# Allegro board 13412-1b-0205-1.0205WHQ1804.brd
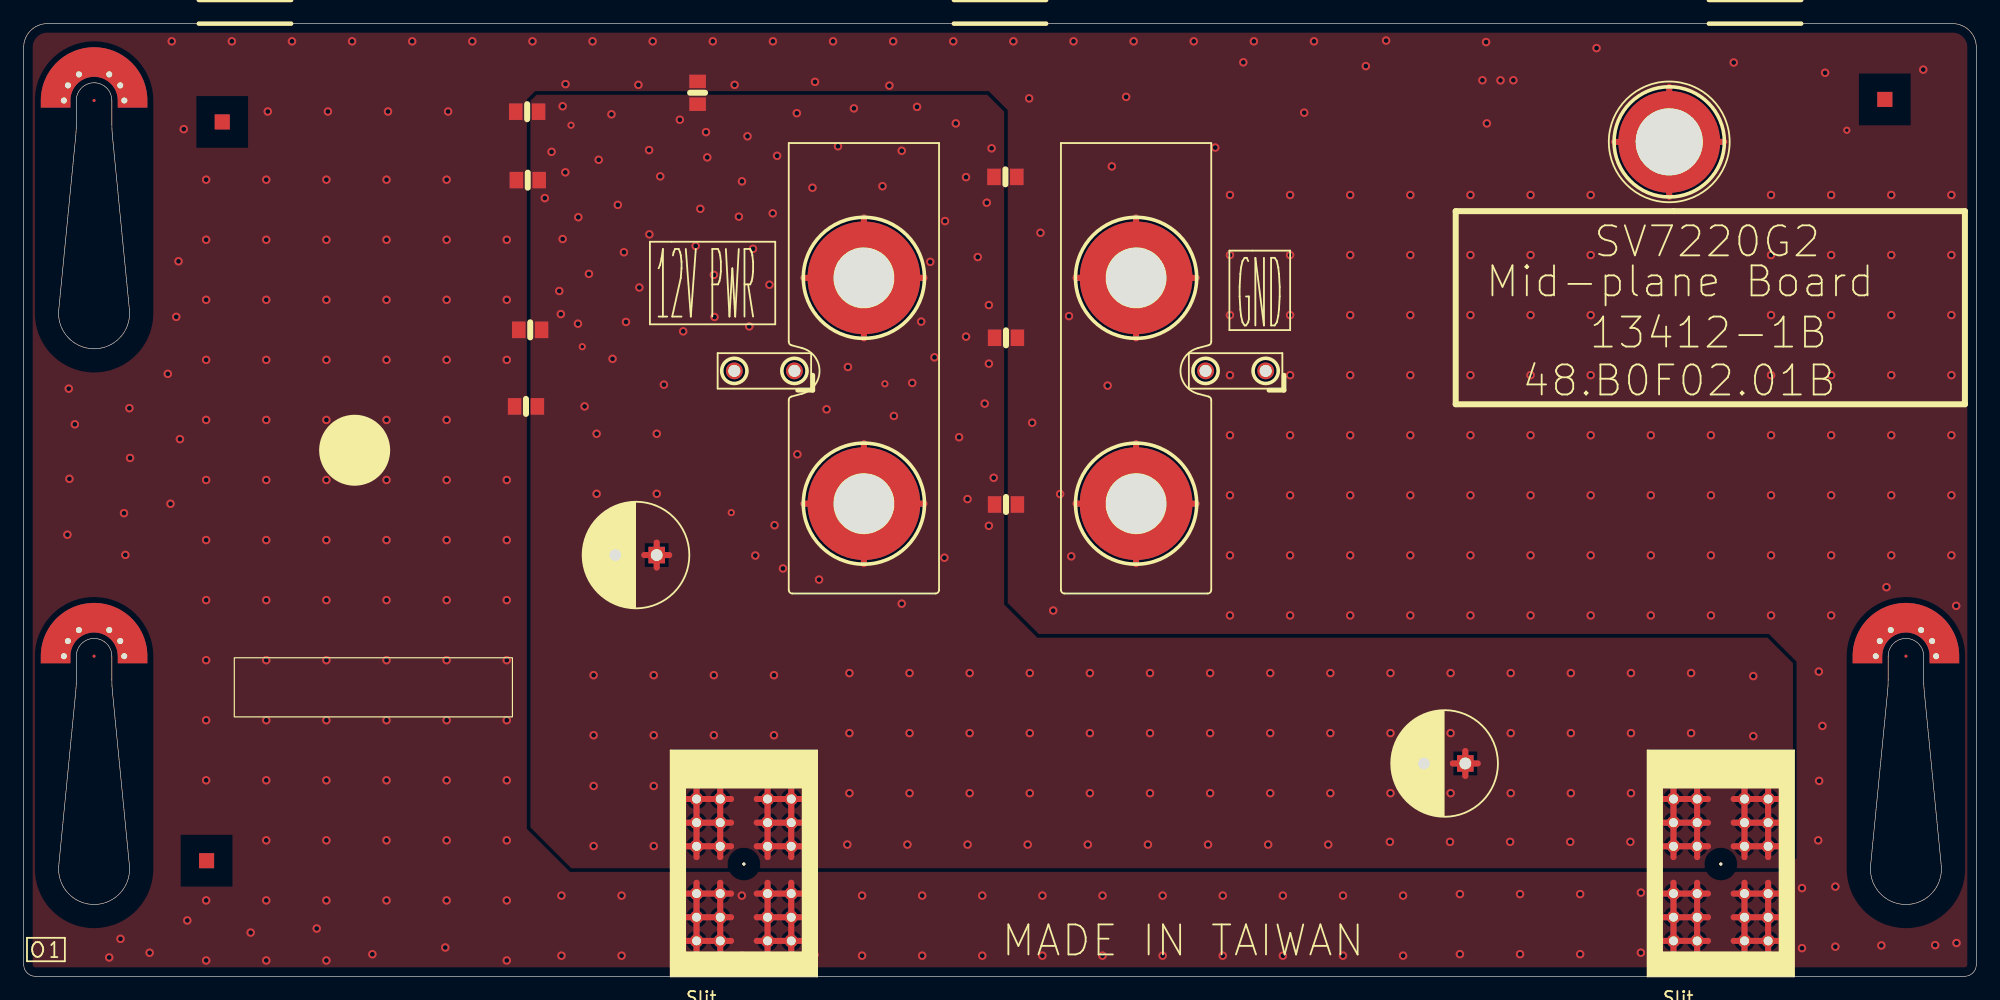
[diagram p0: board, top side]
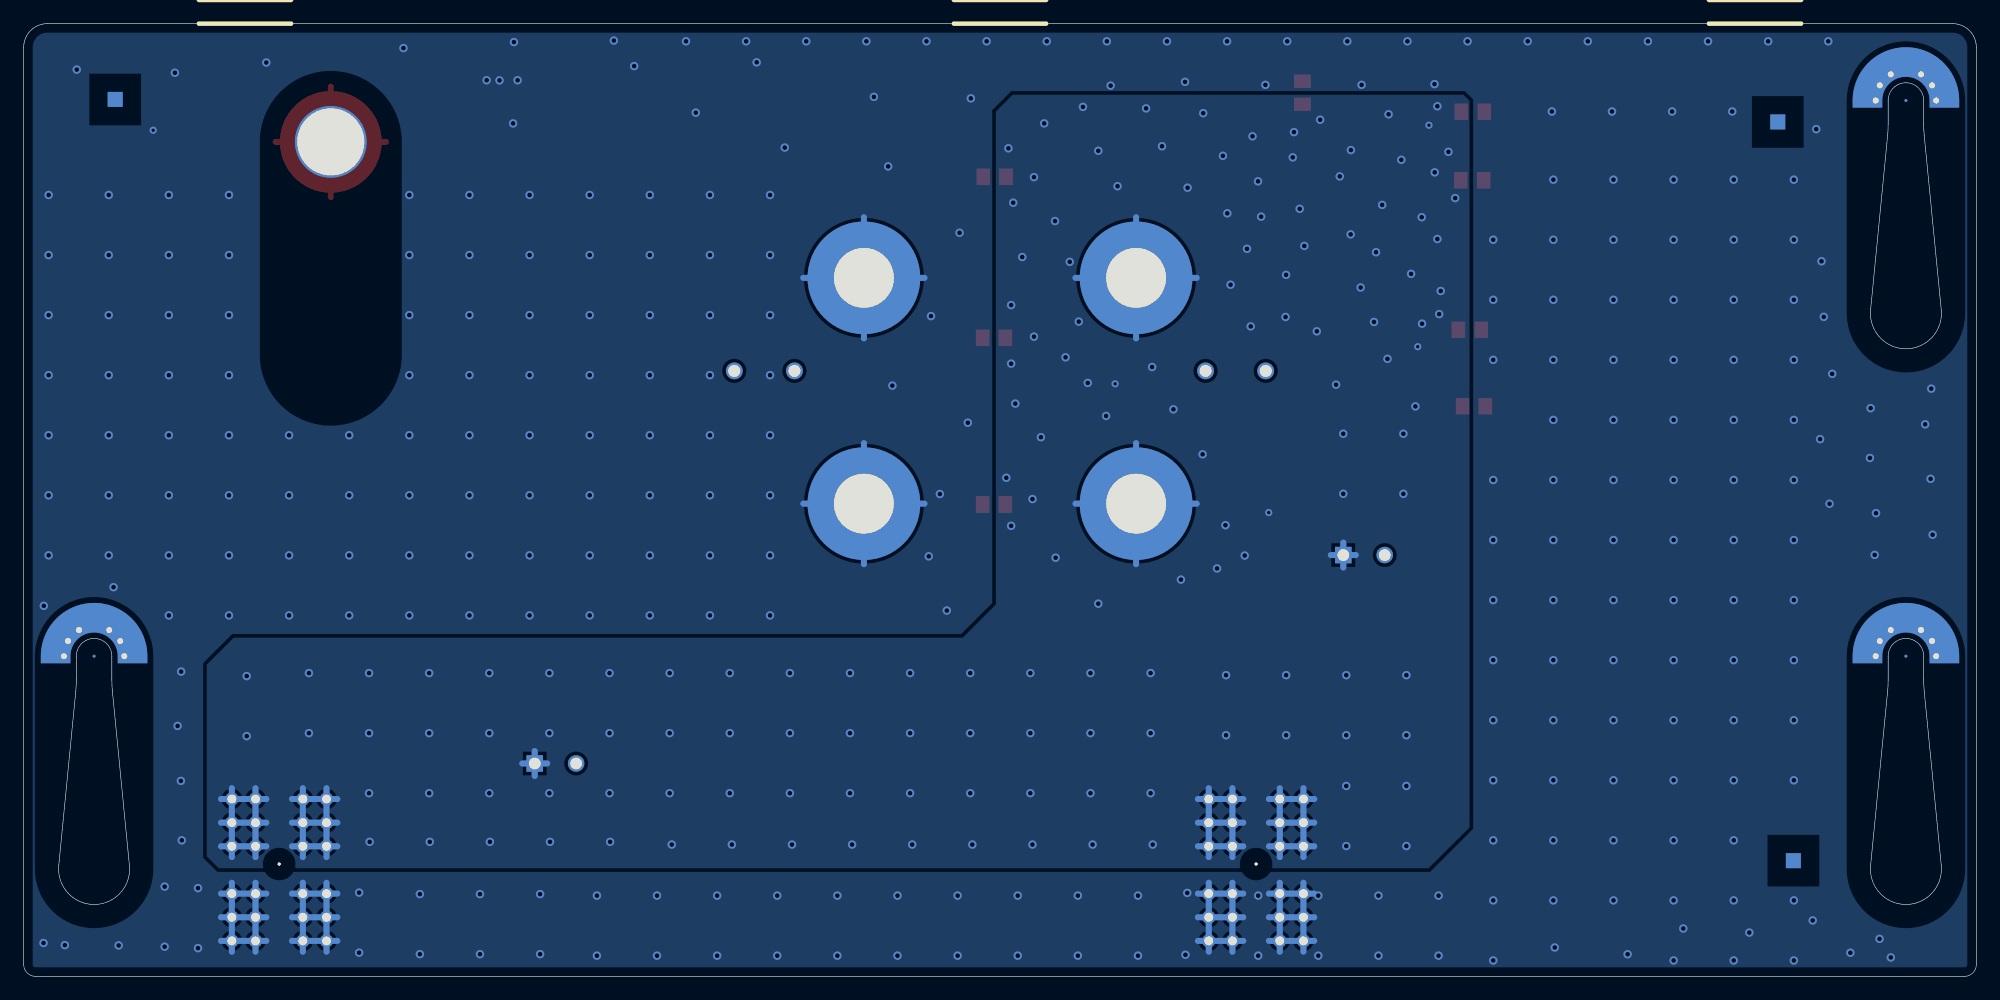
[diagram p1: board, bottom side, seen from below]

Outline 165 x 80.58 mm; copper layers: TOP, L2GND, L3GND, BOTTOM. Coordinates in mm from the lower left corner of the outline.
Outline path: 0,78.58 0,1 arc(0.29,0.29) 1,0 164,0 arc(164.71,0.29) 165,1 165,78.58 arc(164.41,79.99) 163,80.58 2,80.58 arc(0.59,79.99) 0,78.58 ; 2.96,56.37 4.4,71.11 arc(4.44,71.59) 4.45,72.08 4.45,74.08 arc(5.95,75.58) 7.45,74.08 7.45,72.08 arc(7.46,71.59) 7.5,71.11 8.94,56.37 arc(5.95,53.08) 2.96,56.37 ; 2.96,9.37 4.4,24.11 arc(4.44,24.59) 4.45,25.08 4.45,27.08 arc(5.95,28.58) 7.45,27.08 7.45,25.08 arc(7.46,24.59) 7.5,24.11 8.94,9.37 arc(5.95,6.08) 2.96,9.37 ; 156.06,9.37 157.5,24.11 arc(157.54,24.59) 157.55,25.08 157.55,27.08 arc(159.05,28.58) 160.55,27.08 160.55,25.08 arc(160.56,24.59) 160.6,24.11 162.04,9.37 arc(159.05,6.08) 156.06,9.37

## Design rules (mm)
constraint set DEFAULT: min track width 0.127
nets with their own width: min track width 0.508; nets GND

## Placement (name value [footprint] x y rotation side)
BH1  STF375R199H50-GP  [STF375R199H50]  71 59.08 0 top
BH2  STF375R199H50-GP  [STF375R199H50]  71 39.98 0 top
BH3  STF375R199H50-GP  [STF375R199H50]  94 59.08 0 top
BH4  STF375R199H50-GP  [STF375R199H50]  94 39.98 0 top
C1  SC10U25V5KX-GP  [C805H56]  42.55 73.13 270 top
C2  SC10U25V5KX-GP  [C805H56]  83.01 39.91 90 top
C3  SC1U25V5KX-1GP  [C805H58]  82.96 67.62 90 top
C4  SC1U25V5KX-1GP  [C805H58]  83.01 54.01 90 top
C5  SC1U25V5KX-1GP  [C805H58]  42.45 48.21 270 top
C6  SC1U25V5KX-1GP  [C805H58]  42.8 54.68 270 top
C7  SC1U25V5KX-1GP  [C805H58]  56.95 74.73 180 top
C8  SC1U25V5KX-1GP  [C805H58]  42.6 67.34 270 top
CN1  FCI-CONN24-6R-1-GP  [PREFIT-24P-119293H418]  60.86 9.5 0 top
CN2  FCI-CONN24-6R-1-GP  [PREFIT-24P-119293H418]  143.41 9.5 0 top
CN3  AMP-CON2-13-GP  [G800U305032D1EU]  62.59 51.21 180 top
CN4  AMP-CON2-13-GP  [G800U305032D1EU]  102.41 51.21 180 top
H1  GEN276R237X886-6-F-A-S-GP  [GEN276R237X886-6-F-A-S]  5.95 27.08 0 top
H2  STFT339B239R223H453-GP  [STFT339B239R223H453]  139.05 70.58 0 top
H3  GEN276R237X886-6-F-A-S-GP  [GEN276R237X886-6-F-A-S]  159.05 27.08 0 top
H4  GEN276R237X886-6-F-A-S-GP  [GEN276R237X886-6-F-A-S]  5.95 74.08 0 top
NOREF  -  []  1.88 167.43 0 top
NOREF#2  -  []  0 0 0 top
NOREF#3  -  []  0 -1.72 0 top
NOREF#4  -  [unnamed#2]  15.46 9.78 0 top
NOREF#5  -  []  0 -1.72 0 top
NOREF#6  -  [unnamed#2]  16.78 72.27 0 top
NOREF#7  -  []  1.88 2.27 0 top
NOREF#8  -  []  20.14 42.09 0 top
NOREF#9  -  []  0 -1.72 0 top
NOREF#10  -  []  0 -1.72 0 top
NOREF#11  -  []  0 -1.72 0 top
NOREF#12  -  []  0 0 0 top
NOREF#13  -  []  -7 146.48 0 top
NOREF#14  -  [unnamed#2]  157.27 74.17 0 top
NOREF#15  -  []  1.88 84.85 0 top
NOREF#16  -  [unnamed#2]  157.27 74.17 180 bottom
NOREF#17  -  [unnamed#2]  15.46 9.78 180 bottom
NOREF#18  -  [unnamed#2]  16.78 72.27 180 bottom
TC1  E270U16VM-9-GP  [ECAP-138D8H355]  120.07 18.01 90 top
TC2  E270U16VM-9-GP  [ECAP-138D8H355]  51.74 35.63 90 top

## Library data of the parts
BH1-BH4 = STF375R199H50: tolerance: 34.64W05.001
C1 C2 = C805H56: tolerance: 78.10622.51L
C3-C8 = C805H58: tolerance: 78.10522.21L
CN1 CN2 = PREFIT-24P-119293H418: tolerance: 20.82091.024
CN3 CN4 = G800U305032D1EU: tolerance: 25.60037.081
H1 H3 H4 = GEN276R237X886-6-F-A-S: tolerance: ZZ.SCREW.B11
H2 = STFT339B239R223H453: tolerance: ZZ.SCREW.601
TC1 TC2 = ECAP-138D8H355: tolerance: 09.2271D.25L

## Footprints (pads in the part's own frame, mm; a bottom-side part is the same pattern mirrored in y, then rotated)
C805H56
  rect 1.397x1.143 smd: 1(0,0.965) 2(0,-0.965)
C805H58
  rect 1.397x1.143 smd: 1(0,0.965) 2(0,-0.965)
ECAP-138D8H355
  rect 1.397x1.397 hole 0.991: 1(0,-1.75)
  round 1.397 hole 0.991: 2(0,1.75)
G800U305032D1EU
  round 1.422 hole 1.016: 1(-2.54,0) 2(2.54,0)
GEN276R237X886-6-F-A-S
  round 0.254 hole 0.025 unplated: (0,0)
  round 0.864 hole 0.508: 1(2.55,0) 2(2.21,1.28) 3(1.28,2.21) 4(-1.28,2.21) 5(-2.21,1.28) 6(-2.55,0)
PREFIT-24P-119293H418
  round 0.254 hole 2.134 unplated: (0,0)
  round 1.118 hole 0.75: P1_1(-4,1.5) P1_2(-4,3.5) P1_3(-4,5.5) P1_4(-2,1.5) P1_5(-2,3.5) P1_6(-2,5.5) P2_1(4,1.5) P2_2(4,3.5) P2_3(4,5.5) P2_4(2,1.5) P2_5(2,3.5) P2_6(2,5.5) P3_1(4,-6.5) P3_2(4,-4.5) P3_3(4,-2.5) P3_4(2,-6.5) P3_5(2,-4.5) P3_6(2,-2.5) P4_1(-4,-6.5) P4_2(-4,-4.5) P4_3(-4,-2.5) P4_4(-2,-6.5) P4_5(-2,-4.5) P4_6(-2,-2.5)
STF375R199H50
  round 9.525 hole 5.055: 1(0,0)
STFT339B239R223H453
  round 8.611 hole 5.664: 1(0,0)
unnamed#2
  rect 1.27x1.27 smd: (0,0)

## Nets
GND: BH3.1 BH4.1 C1.2 C2.2 C3.2 C4.2 C5.2 C6.2 C7.2 C8.2 CN1.P3_1 CN1.P3_2 CN1.P3_3 CN1.P3_4 CN1.P3_5 CN1.P3_6 CN1.P4_1 CN1.P4_2 CN1.P4_3 CN1.P4_4 CN1.P4_5 CN1.P4_6 CN2.P3_1 CN2.P3_2 CN2.P3_3 CN2.P3_4 CN2.P3_5 CN2.P3_6 CN2.P4_1 CN2.P4_2 CN2.P4_3 CN2.P4_4 CN2.P4_5 CN2.P4_6 H1.1 H1.2 H1.3 H1.4 H1.5 H1.6 H2.1 H3.1 H3.2 H3.3 H3.4 H3.5 H3.6 H4.1 H4.2 H4.3 H4.4 H4.5 H4.6 TC1.2 TC2.2
P12V_MAIN: BH1.1 BH2.1 C1.1 C2.1 C3.1 C4.1 C5.1 C6.1 C7.1 C8.1 CN1.P1_1 CN1.P1_2 CN1.P1_3 CN1.P1_4 CN1.P1_5 CN1.P1_6 CN1.P2_1 CN1.P2_2 CN1.P2_3 CN1.P2_4 CN1.P2_5 CN1.P2_6 CN2.P1_1 CN2.P1_2 CN2.P1_3 CN2.P1_4 CN2.P1_5 CN2.P1_6 CN2.P2_1 CN2.P2_2 CN2.P2_3 CN2.P2_4 CN2.P2_5 CN2.P2_6 TC1.1 TC2.1

Pads without a net: CN3 1 2; CN4 1 2

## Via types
v1: diameter 0.711, hole 0.406, TOP to BOTTOM, 448 vias
v2: diameter 0.61, hole 0.305, TOP to BOTTOM, 5 vias

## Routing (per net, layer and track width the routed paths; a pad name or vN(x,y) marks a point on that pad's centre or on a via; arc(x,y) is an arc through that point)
GND: length 276.2
  TOP w0.508: 139.41,6.09 CN2.P4_3 ; CN2.P4_3 140.32,7 ; CN2.P4_3 138.5,7 ; CN2.P4_3 139.41,7.91 ; CN1.P3_3 64.86,7.91 ; CN1.P3_3 63.95,7 ; CN1.P3_3 65.77,7 ; CN1.P3_3 64.86,6.09 ; 145.41,2.09 CN2.P3_4 ; CN2.P3_4 144.5,3 ; CN2.P3_4 145.41,3.91 ; CN2.P3_4 146.32,3 ; CN2.P4_1 140.32,3 ; CN2.P4_1 139.41,3.91 ; CN2.P4_1 138.5,3 ; CN2.P4_1 139.41,2.09 ; CN1.P4_4 58.86,3.91 ; CN1.P4_4 58.86,2.09 ; CN1.P4_4 59.77,3 ; CN1.P4_4 57.95,3 ; 139.05,65.92 H2.1 ; H2.1 134.39,70.58 ; H2.1 139.05,75.24 ; H2.1 143.71,70.58 ; 140.5,5 CN2.P4_5 ; CN2.P4_5 142.32,5 ; CN2.P4_5 141.41,4.09 ; CN2.P4_5 141.41,5.91 ; CN1.P3_1 65.77,3 ; CN1.P3_1 64.86,3.91 ; CN1.P3_1 64.86,2.09 ; CN1.P3_1 63.95,3 ; BH3.1 94,64.2 ; BH3.1 88.88,59.08 ; BH3.1 94,53.96 ; BH3.1 99.12,59.08 ; CN2.P3_5 146.32,5 ; CN2.P3_5 145.41,5.91 ; CN2.P3_5 144.5,5 ; CN2.P3_5 145.41,4.09 ; 55.95,3 CN1.P4_1 ; CN1.P4_1 57.77,3 ; CN1.P4_1 56.86,3.91 ; CN1.P4_1 56.86,2.09 ; CN1.P3_4 63.77,3 ; CN1.P3_4 61.95,3 ; CN1.P3_4 62.86,2.09 ; CN1.P3_4 62.86,3.91 ; BH4.1 99.12,39.98 ; BH4.1 88.88,39.98 ; BH4.1 94,45.1 ; BH4.1 94,34.86 ; 61.95,5 CN1.P3_5 ; CN1.P3_5 62.86,5.91 ; CN1.P3_5 63.77,5 ; CN1.P3_5 62.86,4.09 ; CN2.P3_6 146.32,7 ; CN2.P3_6 144.5,7 ; CN2.P3_6 145.41,7.91 ; CN2.P3_6 145.41,6.09 ; 140.5,7 CN2.P4_6 ; CN2.P4_6 141.41,7.91 ; CN2.P4_6 142.32,7 ; CN2.P4_6 141.41,6.09 ; CN1.P4_3 57.77,7 ; CN1.P4_3 55.95,7 ; CN1.P4_3 56.86,6.09 ; CN1.P4_3 56.86,7.91 ; CN1.P3_6 62.86,7.91 ; CN1.P3_6 63.77,7 ; CN1.P3_6 61.95,7 ; CN1.P3_6 62.86,6.09 ; CN2.P3_2 147.41,5.91 ; CN2.P3_2 147.41,4.09 ; CN2.P3_2 148.32,5 ; CN2.P3_2 146.5,5 ; CN1.P3_2 65.77,5 ; CN1.P3_2 64.86,5.91 ; CN1.P3_2 64.86,4.09 ; CN1.P3_2 63.95,5 ; CN1.P4_5 59.77,5 ; CN1.P4_5 57.95,5 ; CN1.P4_5 58.86,5.91 ; CN1.P4_5 58.86,4.09 ; 146.5,3 CN2.P3_1 ; CN2.P3_1 148.32,3 ; CN2.P3_1 147.41,2.09 ; CN2.P3_1 147.41,3.91 ; CN1.P4_6 58.86,7.91 ; CN1.P4_6 57.95,7 ; CN1.P4_6 59.77,7 ; CN1.P4_6 58.86,6.09 ; CN2.P4_4 142.32,3 ; CN2.P4_4 141.41,2.09 ; CN2.P4_4 140.5,3 ; CN2.P4_4 141.41,3.91 ; CN2.P4_2 140.32,5 ; CN2.P4_2 138.5,5 ; CN2.P4_2 139.41,5.91 ; CN2.P4_2 139.41,4.09 ; 55.95,5 CN1.P4_2 ; CN1.P4_2 57.77,5 ; CN1.P4_2 56.86,5.91 ; CN1.P4_2 56.86,4.09 ; CN2.P3_3 147.41,7.91 ; CN2.P3_3 148.32,7 ; CN2.P3_3 146.5,7 ; CN2.P3_3 147.41,6.09
  BOTTOM w0.508: 56.86,2.09 CN1.P4_1 ; CN1.P4_1 55.95,3 ; CN1.P4_1 56.86,3.91 ; CN1.P4_1 57.77,3 ; 146.5,7 CN2.P3_3 ; CN2.P3_3 148.32,7 ; CN2.P3_3 147.41,7.91 ; CN2.P3_3 147.41,6.09 ; 147.41,2.09 CN2.P3_1 ; CN2.P3_1 147.41,3.91 ; CN2.P3_1 148.32,3 ; CN2.P3_1 146.5,3 ; 58.86,2.09 CN1.P4_4 ; CN1.P4_4 57.95,3 ; CN1.P4_4 59.77,3 ; CN1.P4_4 58.86,3.91 ; CN2.P4_4 141.41,3.91 ; CN2.P4_4 142.32,3 ; CN2.P4_4 141.41,2.09 ; CN2.P4_4 140.5,3 ; 140.5,5 CN2.P4_5 ; CN2.P4_5 141.41,5.91 ; CN2.P4_5 141.41,4.09 ; CN2.P4_5 142.32,5 ; 56.86,4.09 CN1.P4_2 ; CN1.P4_2 57.77,5 ; CN1.P4_2 56.86,5.91 ; CN1.P4_2 55.95,5 ; 94,34.86 BH4.1 ; BH4.1 94,45.1 ; BH4.1 88.88,39.98 ; BH4.1 99.12,39.98 ; 61.95,7 CN1.P3_6 ; CN1.P3_6 62.86,7.91 ; CN1.P3_6 63.77,7 ; CN1.P3_6 62.86,6.09 ; CN2.P3_5 146.32,5 ; CN2.P3_5 145.41,5.91 ; CN2.P3_5 145.41,4.09 ; CN2.P3_5 144.5,5 ; CN1.P3_5 62.86,5.91 ; CN1.P3_5 61.95,5 ; CN1.P3_5 63.77,5 ; CN1.P3_5 62.86,4.09 ; CN2.P3_6 146.32,7 ; CN2.P3_6 145.41,7.91 ; CN2.P3_6 145.41,6.09 ; CN2.P3_6 144.5,7 ; CN1.P3_4 63.77,3 ; CN1.P3_4 62.86,2.09 ; CN1.P3_4 61.95,3 ; CN1.P3_4 62.86,3.91 ; CN1.P4_6 58.86,7.91 ; CN1.P4_6 59.77,7 ; CN1.P4_6 57.95,7 ; CN1.P4_6 58.86,6.09 ; 56.86,6.09 CN1.P4_3 ; CN1.P4_3 57.77,7 ; CN1.P4_3 55.95,7 ; CN1.P4_3 56.86,7.91 ; 138.5,5 CN2.P4_2 ; CN2.P4_2 140.32,5 ; CN2.P4_2 139.41,5.91 ; CN2.P4_2 139.41,4.09 ; 64.86,6.09 CN1.P3_3 ; CN1.P3_3 63.95,7 ; CN1.P3_3 65.77,7 ; CN1.P3_3 64.86,7.91 ; CN2.P3_2 147.41,5.91 ; CN2.P3_2 148.32,5 ; CN2.P3_2 146.5,5 ; CN2.P3_2 147.41,4.09 ; 88.88,59.08 BH3.1 ; BH3.1 94,53.96 ; BH3.1 94,64.2 ; BH3.1 99.12,59.08 ; 57.95,5 CN1.P4_5 ; CN1.P4_5 58.86,5.91 ; CN1.P4_5 58.86,4.09 ; CN1.P4_5 59.77,5 ; CN1.P3_1 64.86,3.91 ; CN1.P3_1 64.86,2.09 ; CN1.P3_1 63.95,3 ; CN1.P3_1 65.77,3 ; CN2.P3_4 146.32,3 ; CN2.P3_4 144.5,3 ; CN2.P3_4 145.41,3.91 ; CN2.P3_4 145.41,2.09 ; CN2.P4_1 139.41,3.91 ; CN2.P4_1 138.5,3 ; CN2.P4_1 140.32,3 ; CN2.P4_1 139.41,2.09 ; CN2.P4_3 140.32,7 ; CN2.P4_3 139.41,7.91 ; CN2.P4_3 139.41,6.09 ; CN2.P4_3 138.5,7 ; CN2.P4_6 141.41,7.91 ; CN2.P4_6 141.41,6.09 ; CN2.P4_6 142.32,7 ; CN2.P4_6 140.5,7 ; CN1.P3_2 65.77,5 ; CN1.P3_2 64.86,5.91 ; CN1.P3_2 63.95,5 ; CN1.P3_2 64.86,4.09
  vias: v1(3.7,37.36) v1(3.81,49.71) v1(3.87,42.08) v1(4.32,46.69) v1(7.23,1.6) v1(8.18,3.17) v1(8.48,39.18) v1(8.59,35.65) v1(8.93,48.06) v1(8.99,43.84) v1(10.64,2) v1(12.18,50.96) v1(12.41,39.97) v1(12.51,79.09) v1(12.89,55.78) v1(13.08,60.48) v1(13.2,45.44) v1(13.53,71.66) v1(13.83,4.73) v1(15.42,67.38) v1(15.42,62.3) v1(15.42,57.22) v1(15.42,52.14) v1(15.42,47.06) v1(15.42,41.98) v1(15.42,36.9) v1(15.42,31.82) v1(15.42,26.74) v1(15.42,21.66) v1(15.42,16.58) v1(15.42,6.42) v1(15.42,1.34) v1(17.59,79.09) v1(19.18,3.7) v1(20.5,67.38) v1(20.5,62.3) v1(20.5,57.22) v1(20.5,52.14) v1(20.5,47.06) v1(20.5,41.98) v1(20.5,36.9) v1(20.5,31.82) v1(20.5,26.74) v1(20.5,21.66) v1(20.5,16.58) v1(20.5,11.5) v1(20.5,6.42) v1(20.5,1.34) v1(20.63,73.15) v1(22.67,79.09) v1(24.76,4.04) v1(25.58,67.38) v1(25.58,62.3) v1(25.58,57.22) v1(25.58,52.14) v1(25.58,47.06) v1(25.58,41.98) v1(25.58,36.9) v1(25.58,31.82) v1(25.58,26.74) v1(25.58,21.66) v1(25.58,16.58) v1(25.58,11.5) v1(25.58,6.42) v1(25.58,1.34) v1(25.71,73.15) v1(27.75,79.09) v1(29.47,1.87) v1(30.66,67.38) v1(30.66,62.3) v1(30.66,57.22) v1(30.66,52.14) v1(30.66,47.06) v1(30.66,41.98) v1(30.66,36.9) v1(30.66,31.82) v1(30.66,26.74) v1(30.66,21.66) v1(30.66,16.58) v1(30.66,11.5) v1(30.66,6.42) v1(30.79,73.15) v1(32.83,79.09) v1(35.63,2.44) v1(35.74,67.38) v1(35.74,62.3) v1(35.74,57.22) v1(35.74,52.14) v1(35.74,47.06) v1(35.74,41.98) v1(35.74,36.9) v1(35.74,31.82) v1(35.74,26.74) v1(35.74,21.66) v1(35.74,16.58) v1(35.74,11.5) v1(35.74,6.42) v1(35.87,73.15) v1(37.91,79.09) v1(40.82,62.3) v1(40.82,57.22) v1(40.82,52.14) v1(40.82,41.98) v1(40.82,36.9) v1(40.82,31.82) v1(40.82,26.74) v1(40.82,21.66) v1(40.82,16.58) v1(40.82,11.5) v1(40.82,6.42) v1(40.82,1.34) v1(42.99,79.09) v1(45.44,6.83) v1(45.44,1.75) v1(45.79,75.47) v1(48.07,79.09) v1(50.52,6.83) v1(50.52,1.75) v1(51.95,75.4) v1(53.15,79.09) v1(55.6,6.83) v1(55.6,1.75) v1(58.23,79.09) v1(60.07,75.4) v1(60.68,6.83) v1(60.68,1.75) v1(63.31,79.09) v1(66.68,7.06) v1(66.83,1.83) v1(66.87,75.66) v1(68.39,79.09) v1(70.84,6.83) v1(70.84,1.75) v1(73.15,75.34) v1(73.47,79.09) v1(75.92,6.83) v1(75.92,1.75) v1(78.55,79.09) v1(81,6.83) v1(81,1.75) v1(83.63,79.09) v1(84.97,74.26) v1(85.22,46.83) v1(85.92,62.89) v1(86.08,6.83) v1(86.08,1.75) v1(87,30.94) v1(87.58,40.79) v1(88.33,55.84) v1(88.52,35.52) v1(88.71,79.09) v1(91.16,6.83) v1(91.16,1.75) v1(91.59,49.96) v1(91.95,68.51) v1(93.16,74.39) v1(93.79,79.09) v1(96.24,6.83) v1(96.24,1.75) v1(98.87,79.09) v1(100.69,70.1) v1(101.32,6.83) v1(101.32,1.75) v1(101.93,66.09) v1(101.93,61.01) v1(101.93,55.93) v1(101.93,50.85) v1(101.93,45.77) v1(101.93,40.69) v1(101.93,35.61) v1(101.93,30.53) v1(103.06,77.31) v1(103.95,79.09) v1(106.4,6.83) v1(106.4,1.75) v1(107.01,66.09) v1(107.01,61.01) v1(107.01,55.93) v1(107.01,50.85) v1(107.01,45.77) v1(107.01,40.69) v1(107.01,35.61) v1(107.01,30.53) v1(108.21,73.05) v1(109.03,79.09) v1(111.48,6.83) v1(111.48,1.75) v1(112.09,66.09) v1(112.09,61.01) v1(112.09,55.93) v1(112.09,50.85) v1(112.09,45.77) v1(112.09,40.69) v1(112.09,35.61) v1(112.09,30.53) v1(113.41,76.99) v1(115.13,79.15) v1(116.56,6.83) v1(116.56,1.75) v1(117.17,66.09) v1(117.17,61.01) v1(117.17,55.93) v1(117.17,50.85) v1(117.17,45.77) v1(117.17,40.69) v1(117.17,35.61) v1(117.17,30.53) v1(121.36,6.96) v1(121.36,1.88) v1(122.25,66.09) v1(122.25,61.01) v1(122.25,55.93) v1(122.25,50.85) v1(122.25,45.77) v1(122.25,40.69) v1(122.25,35.61) v1(122.25,30.53) v1(123.27,75.79) v1(123.57,79.02) v1(123.64,72.14) v1(124.79,75.78) v1(125.88,75.79) v1(126.44,6.96) v1(126.44,1.88) v1(127.33,66.09) v1(127.33,61.01) v1(127.33,55.93) v1(127.33,50.85) v1(127.33,45.77) v1(127.33,40.69) v1(127.33,35.61) v1(127.33,30.53) v1(131.52,6.96) v1(131.52,1.88) v1(132.41,66.09) v1(132.41,61.01) v1(132.41,55.93) v1(132.41,50.85) v1(132.41,45.77) v1(132.41,40.69) v1(132.41,35.61) v1(132.41,30.53) v1(132.91,78.51) v1(136.65,7.08) v1(136.65,2) v1(137.49,45.77) v1(137.49,40.69) v1(137.49,35.61) v1(137.49,30.53) v1(142.57,45.77) v1(142.57,40.69) v1(142.57,35.61) v1(142.57,30.53) v1(144.5,77.29) v1(147.65,66.09) v1(147.65,61.01) v1(147.65,55.93) v1(147.65,50.85) v1(147.65,45.77) v1(147.65,40.69) v1(147.65,35.61) v1(147.65,30.53) v1(150.27,7.46) v1(150.27,2.38) v1(151.64,11.5) v1(151.69,25.78) v1(151.72,16.53) v1(152,21.18) v1(152.22,76.43) v1(152.73,66.09) v1(152.73,61.01) v1(152.73,55.93) v1(152.73,50.85) v1(152.73,45.77) v1(152.73,40.69) v1(152.73,35.61) v1(152.73,30.53) v1(153.09,7.59) v1(153.09,2.51) v1(156.97,2.61) v1(157.41,32.92) v1(157.81,66.09) v1(157.81,61.01) v1(157.81,55.93) v1(157.81,50.85) v1(157.81,45.77) v1(157.81,40.69) v1(157.81,35.61) v1(160.52,76.69) v1(161.52,2.64) v1(162.89,66.09) v1(162.89,61.01) v1(162.89,55.93) v1(162.89,50.85) v1(162.89,45.77) v1(162.89,40.69) v1(162.89,35.61) v1(163.3,31.34) v1(163.32,2.82) v2(154.06,71.57)
P12V_MAIN: length 274.4
  TOP w0.508: 145.41,10.09 CN2.P2_4 ; CN2.P2_4 144.5,11 ; CN2.P2_4 145.41,11.92 ; CN2.P2_4 146.32,11 ; 55.95,13 CN1.P1_2 ; CN1.P1_2 56.86,13.92 ; CN1.P1_2 57.77,13 ; CN1.P1_2 56.86,12.09 ; CN2.P1_4 142.32,11 ; CN2.P1_4 141.41,10.09 ; CN2.P1_4 140.5,11 ; CN2.P1_4 141.41,11.92 ; 147.41,12.09 CN2.P2_2 ; CN2.P2_2 146.5,13 ; CN2.P2_2 147.41,13.92 ; CN2.P2_2 148.32,13 ; CN2.P1_1 140.32,11 ; CN2.P1_1 138.5,11 ; CN2.P1_1 139.41,11.92 ; CN2.P1_1 139.41,10.09 ; TC2.1 54.55,35.63 ; TC2.1 52.44,35.63 ; TC2.1 53.49,36.69 ; TC2.1 53.49,34.58 ; 65.88,39.98 BH2.1 ; BH2.1 71,34.86 ; BH2.1 71,45.1 ; BH2.1 76.12,39.98 ; 58.86,12.09 CN1.P1_5 ; CN1.P1_5 59.77,13 ; CN1.P1_5 57.95,13 ; CN1.P1_5 58.86,13.92 ; 121.82,16.95 TC1.1 ; TC1.1 120.76,18.01 ; TC1.1 121.82,19.06 ; TC1.1 122.87,18.01 ; 63.95,15 CN1.P2_3 ; CN1.P2_3 64.86,15.92 ; CN1.P2_3 65.77,15 ; CN1.P2_3 64.86,14.09 ; CN1.P1_4 58.86,11.92 ; CN1.P1_4 59.77,11 ; CN1.P1_4 57.95,11 ; CN1.P1_4 58.86,10.09 ; 64.86,10.09 CN1.P2_1 ; CN1.P2_1 65.77,11 ; CN1.P2_1 64.86,11.92 ; CN1.P2_1 63.95,11 ; CN1.P2_5 63.77,13 ; CN1.P2_5 61.95,13 ; CN1.P2_5 62.86,12.09 ; CN1.P2_5 62.86,13.92 ; CN2.P2_1 147.41,11.92 ; CN2.P2_1 147.41,10.09 ; CN2.P2_1 146.5,11 ; CN2.P2_1 148.32,11 ; CN2.P2_3 148.32,15 ; CN2.P2_3 147.41,14.09 ; CN2.P2_3 147.41,15.92 ; CN2.P2_3 146.5,15 ; 61.95,15 CN1.P2_6 ; CN1.P2_6 63.77,15 ; CN1.P2_6 62.86,14.09 ; CN1.P2_6 62.86,15.92 ; CN2.P1_5 142.32,13 ; CN2.P1_5 141.41,13.92 ; CN2.P1_5 141.41,12.09 ; CN2.P1_5 140.5,13 ; CN1.P1_1 57.77,11 ; CN1.P1_1 56.86,11.92 ; CN1.P1_1 55.95,11 ; CN1.P1_1 56.86,10.09 ; 62.86,10.09 CN1.P2_4 ; CN1.P2_4 62.86,11.92 ; CN1.P2_4 63.77,11 ; CN1.P2_4 61.95,11 ; CN2.P1_3 140.32,15 ; CN2.P1_3 139.41,14.09 ; CN2.P1_3 138.5,15 ; CN2.P1_3 139.41,15.92 ; 145.41,12.09 CN2.P2_5 ; CN2.P2_5 145.41,13.92 ; CN2.P2_5 144.5,13 ; CN2.P2_5 146.32,13 ; 58.86,14.09 CN1.P1_6 ; CN1.P1_6 58.86,15.92 ; CN1.P1_6 57.95,15 ; CN1.P1_6 59.77,15 ; 144.5,15 CN2.P2_6 ; CN2.P2_6 145.41,15.92 ; CN2.P2_6 145.41,14.09 ; CN2.P2_6 146.32,15 ; BH1.1 76.12,59.08 ; BH1.1 65.88,59.08 ; BH1.1 71,64.2 ; BH1.1 71,53.96 ; CN2.P1_2 140.32,13 ; CN2.P1_2 139.41,12.09 ; CN2.P1_2 139.41,13.92 ; CN2.P1_2 138.5,13 ; CN1.P2_2 64.86,13.92 ; CN1.P2_2 65.77,13 ; CN1.P2_2 63.95,13 ; CN1.P2_2 64.86,12.09 ; CN2.P1_6 142.32,15 ; CN2.P1_6 141.41,14.09 ; CN2.P1_6 140.5,15 ; CN2.P1_6 141.41,15.92 ; 55.95,15 CN1.P1_3 ; CN1.P1_3 57.77,15 ; CN1.P1_3 56.86,14.09 ; CN1.P1_3 56.86,15.92
  BOTTOM w0.508: BH2.1 76.12,39.98 ; BH2.1 71,45.1 ; BH2.1 71,34.86 ; BH2.1 65.88,39.98 ; 56.86,10.09 CN1.P1_1 ; CN1.P1_1 57.77,11 ; CN1.P1_1 56.86,11.92 ; CN1.P1_1 55.95,11 ; CN1.P2_6 62.86,15.92 ; CN1.P2_6 63.77,15 ; CN1.P2_6 62.86,14.09 ; CN1.P2_6 61.95,15 ; 139.41,10.09 CN2.P1_1 ; CN2.P1_1 138.5,11 ; CN2.P1_1 140.32,11 ; CN2.P1_1 139.41,11.92 ; 145.41,12.09 CN2.P2_5 ; CN2.P2_5 144.5,13 ; CN2.P2_5 145.41,13.92 ; CN2.P2_5 146.32,13 ; CN1.P2_1 65.77,11 ; CN1.P2_1 63.95,11 ; CN1.P2_1 64.86,11.92 ; CN1.P2_1 64.86,10.09 ; CN1.P1_2 57.77,13 ; CN1.P1_2 56.86,12.09 ; CN1.P1_2 56.86,13.92 ; CN1.P1_2 55.95,13 ; 147.41,10.09 CN2.P2_1 ; CN2.P2_1 148.32,11 ; CN2.P2_1 147.41,11.92 ; CN2.P2_1 146.5,11 ; CN2.P1_4 141.41,11.92 ; CN2.P1_4 142.32,11 ; CN2.P1_4 141.41,10.09 ; CN2.P1_4 140.5,11 ; CN2.P2_6 145.41,15.92 ; CN2.P2_6 144.5,15 ; CN2.P2_6 146.32,15 ; CN2.P2_6 145.41,14.09 ; 146.5,13 CN2.P2_2 ; CN2.P2_2 148.32,13 ; CN2.P2_2 147.41,13.92 ; CN2.P2_2 147.41,12.09 ; CN2.P1_5 142.32,13 ; CN2.P1_5 140.5,13 ; CN2.P1_5 141.41,12.09 ; CN2.P1_5 141.41,13.92 ; CN2.P2_3 147.41,15.92 ; CN2.P2_3 148.32,15 ; CN2.P2_3 147.41,14.09 ; CN2.P2_3 146.5,15 ; 62.86,12.09 CN1.P2_5 ; CN1.P2_5 63.77,13 ; CN1.P2_5 62.86,13.92 ; CN1.P2_5 61.95,13 ; 139.41,14.09 CN2.P1_3 ; CN2.P1_3 140.32,15 ; CN2.P1_3 138.5,15 ; CN2.P1_3 139.41,15.92 ; 55.95,15 CN1.P1_3 ; CN1.P1_3 56.86,14.09 ; CN1.P1_3 56.86,15.92 ; CN1.P1_3 57.77,15 ; 58.86,10.09 CN1.P1_4 ; CN1.P1_4 58.86,11.92 ; CN1.P1_4 57.95,11 ; CN1.P1_4 59.77,11 ; CN1.P1_5 58.86,13.92 ; CN1.P1_5 57.95,13 ; CN1.P1_5 59.77,13 ; CN1.P1_5 58.86,12.09 ; TC2.1 53.49,36.69 ; TC2.1 53.49,34.58 ; TC2.1 52.44,35.63 ; TC2.1 54.55,35.63 ; 64.86,12.09 CN1.P2_2 ; CN1.P2_2 65.77,13 ; CN1.P2_2 64.86,13.92 ; CN1.P2_2 63.95,13 ; TC1.1 122.87,18.01 ; TC1.1 120.76,18.01 ; TC1.1 121.82,19.06 ; TC1.1 121.82,16.95 ; 141.41,14.09 CN2.P1_6 ; CN2.P1_6 142.32,15 ; CN2.P1_6 141.41,15.92 ; CN2.P1_6 140.5,15 ; 63.95,15 CN1.P2_3 ; CN1.P2_3 64.86,15.92 ; CN1.P2_3 65.77,15 ; CN1.P2_3 64.86,14.09 ; 62.86,10.09 CN1.P2_4 ; CN1.P2_4 62.86,11.92 ; CN1.P2_4 61.95,11 ; CN1.P2_4 63.77,11 ; 57.95,15 CN1.P1_6 ; CN1.P1_6 58.86,14.09 ; CN1.P1_6 58.86,15.92 ; CN1.P1_6 59.77,15 ; 138.5,13 CN2.P1_2 ; CN2.P1_2 139.41,13.92 ; CN2.P1_2 139.41,12.09 ; CN2.P1_2 140.32,13 ; 144.5,11 CN2.P2_4 ; CN2.P2_4 145.41,11.92 ; CN2.P2_4 145.41,10.09 ; CN2.P2_4 146.32,11 ; 65.88,59.08 BH1.1 ; BH1.1 71,64.2 ; BH1.1 71,53.96 ; BH1.1 76.12,59.08
  vias: v1(44.04,65.83) v1(44.61,69.74) v1(45.26,57.97) v1(45.39,56.01) v1(45.54,73.59) v1(45.54,62.36) v1(45.77,68) v1(46.84,55.2) v1(46.87,64.21) v1(47.4,48.21) v1(47.76,59.41) v1(48.16,25.47) v1(48.16,20.39) v1(48.16,16.1) v1(48.16,11.02) v1(48.41,45.9) v1(48.41,40.82) v1(48.59,69.06) v1(49.67,72.91) v1(49.76,52.23) v1(50.21,65.25) v1(50.72,61.25) v1(50.9,55.35) v1(52.03,58.26) v1(52.85,69.89) v1(52.87,62.76) v1(53.24,25.47) v1(53.24,20.39) v1(53.24,16.1) v1(53.24,11.02) v1(53.49,45.9) v1(53.49,40.82) v1(53.79,67.66) v1(54.1,50.05) v1(55.45,72.45) v1(55.73,54.56) v1(56.78,61.78) v1(57.18,64.92) v1(57.66,71.41) v1(57.76,69.27) v1(58.33,59.33) v1(58.32,25.47) v1(58.32,20.39) v1(58.37,55.77) v1(60.43,64.25) v1(60.7,67.24) v1(61.16,71.05) v1(61.32,54.97) v1(61.63,61.54) v1(61.82,35.59) v1(63.02,58.5) v1(63.29,64.54) v1(63.45,38.16) v1(63.4,25.47) v1(63.4,20.39) v1(63.66,69.4) v1(64.16,34.5) v1(65.33,73.01) v1(65.38,44.15) v1(66.65,66.7) v1(67.21,33.56) v1(67.85,47.96) v1(68.81,70.21) v1(69.65,51.54) v1(69.6,11.15) v1(69.78,25.65) v1(69.78,20.57) v1(69.78,15.49) v1(70.15,73.41) v1(72.57,66.83) v1(73.54,47.4) v1(74.2,69.83) v1(74.2,31.52) v1(74.68,11.15) v1(74.86,25.65) v1(74.86,20.57) v1(74.86,15.49) v1(75.08,50.19) v1(75.49,73.54) v1(75.84,55.38) v1(76.61,60.43) v1(76.96,52.36) v1(77.8,35.41) v1(77.85,63.88) v1(78.77,72.14) v1(79.04,45.6) v1(79.63,67.6) v1(79.63,54.11) v1(79.76,40.37) v1(79.76,11.15) v1(79.94,25.65) v1(79.94,20.57) v1(79.94,15.49) v1(80.62,60.84) v1(81.2,48.44) v1(81.38,65.44) v1(81.56,56.78) v1(81.56,51.82) v1(81.56,38.11) v1(81.79,70.03) v1(81.97,42.17) v1(84.84,11.15) v1(85.02,25.65) v1(85.02,20.57) v1(85.02,15.49) v1(89.92,11.15) v1(90.1,25.65) v1(90.1,20.57) v1(90.1,15.49) v1(95,11.15) v1(95.18,25.65) v1(95.18,20.57) v1(95.18,15.49) v1(100.08,11.15) v1(100.26,25.65) v1(100.26,20.57) v1(100.26,15.49) v1(105.16,11.15) v1(105.34,25.65) v1(105.34,20.57) v1(105.34,15.49) v1(110.24,11.15) v1(110.42,25.65) v1(110.42,20.57) v1(110.42,15.49) v1(115.45,11.38) v1(115.5,25.65) v1(115.5,20.57) v1(115.5,15.49) v1(120.53,11.38) v1(120.58,25.65) v1(120.58,20.57) v1(120.58,15.49) v1(125.61,11.38) v1(125.66,25.65) v1(125.66,20.57) v1(125.66,15.49) v1(130.74,25.65) v1(130.74,20.57) v1(130.74,15.49) v1(130.69,11.38) v1(135.82,25.65) v1(135.82,20.57) v1(135.82,15.49) v1(135.77,11.38) v1(140.9,25.65) v1(140.9,20.57) v1(146.15,25.4) v1(146.15,20.32) v2(46.25,71.99) v2(47.2,53.26) v2(59.79,39.22) v2(72.77,50.12)

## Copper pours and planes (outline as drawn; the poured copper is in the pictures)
GND on TOP, BOTTOM, L3GND: 1,0.76 0.83,0.83 0.76,1 0.76,78.58 1.13,79.45 2,79.82 163,79.82 163.87,79.45 164.24,78.58 164.24,1 164.17,0.83 164,0.76
GND on L2GND: 1,0.76 0.83,0.83 0.76,1 0.76,78.58 1.13,79.45 2,79.82 163,79.82 163.87,79.45 164.24,78.58 164.24,1 164.17,0.83 164,0.76 ; 1 cut-out
P12V_MAIN on TOP: 42.82,74.05 43.35,74.57 81.42,74.57 82.85,73.14 82.85,31.45 85.65,28.65 147.35,28.65 149.51,26.49 149.51,10.13 148.52,9.14 46.28,9.14 42.82,12.6
P12V_MAIN on BOTTOM: 42.82,74.05 43.35,74.57 81.42,74.57 82.85,73.14 82.85,31.45 85.65,28.65 147.25,28.65 149.53,26.36 149.53,10.16 148.52,9.14 46.28,9.14 42.82,12.6
P12V_MAIN on L2GND: 46.31,9.24 42.93,12.62 42.93,74.01 43.36,74.44 81.41,74.44 82.73,73.12 82.73,31.44 85.62,28.55 147.29,28.55 149.4,26.44 149.4,10.16 148.49,9.24

Small or netless copper shapes (teardrops, artwork), in the pictures only: 3 on TOP, 3 on BOTTOM

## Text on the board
Ref Des/Silkscreen Top: 12V PWR | GND | MADE IN TAIWAN | Mid-plane Board | 48.B0F02.01B | 13412-1B | SV7220G2
User.23: ByImpedance:50.0@_REF_L1=("6.5(L1)")|_REF_L6=("6.5(L6)")|Type="SE"|imp="50.0" | ByImpedance:60.0@_REF_L1=("4.5(L1)")|_REF_L6=("4.5(L6)")|Type="SE"|imp="60.0" | LayerIndex:nil | Source:F11DRH1_Power_Board_Stack_up_2oz_20120822_Arthur.xls | artWorks:("_REF_L6" "_REF_L1") | gtImpOutlineUsed:BOARD GEOMETRY/PANEL_OUTLINE
User.24: BGA From Routing Tab Check,Aug 27 17:56:39 2012,Warning | Board Accuracy Check,Jun 11 11:29:38 2013,Passed | Broken Plane Check,Aug 27 18:06:41 2012,Passed | Capacitor Orrientation Check,Aug 27 17:56:39 2012,Passed | Comp From Routing Tab Check,Aug 27 17:56:40 2012,Passed | Comp Pad To Comp Pad Check,Aug 27 17:56:39 2012,10 errors | Component On Edge Check,Aug 27 17:56:39 2012,12 errors | Component Overlap Check,Aug 27 17:56:39 2012,4 errors | Component[Pitch] On Edge Check,Aug 27 17:56:39 2012,Warning | DFT Requirements,Aug 27 18:06:49 2012,7 errors | DIMM 10mm Area Check,Aug 27 17:56:40 2012,Warning | Dummy-Static-No Shape On Layer Check,Jun 11 11:29:39 2013,Passed | Height Limit Check,Aug 27 17:56:40 2012,12 errors | LF HASL Via Check,Aug 27 18:03:00 2012,372 errors | Library Path Check,Aug 27 17:56:40 2012,13 errors | Markin Check,Aug 27 17:56:40 2012,Passed | Markout And Tooling Hole Check,Aug 27 17:56:40 2012,12 errors | Placement Balance Check,Aug 27 17:56:40 2012,Passed | Small Comp Near Big Comp Check,Aug 27 17:56:40 2012,6 errors | Split Plane Check,Aug 27 18:18:31 2012,Passed | TP Percentage Check,Aug 27 18:06:48 2012,Passed | TP To Golden Finger Check,Aug 27 18:06:48 2012,Warning | TP Violations Check,Aug 27 18:06:49 2012,36 errors | Thermal Reduction Check,Aug 27 18:06:42 2012,Passed | Thru Pin To SMD Clearance Check,Aug 27 17:56:40 2012,Passed | Thru Pin To Thru Via Check,Aug 27 18:06:42 2012,Passed | Via Aspect Ratio Check,Aug 27 18:03:01 2012,6 errors | Via Connectivity,Aug 27 18:03:01 2012,2 errors | Via On Moat Check,Aug 27 18:03:00 2012,2 errors | Via On Pad Check,Aug 27 18:03:00 2012,6 errors | Via To Via Per Net Check,Aug 27 18:03:01 2012,Warning | Via To Via Spacing Check,Aug 27 18:03:01 2012,39 errors | Via Type Check,Aug 27 18:03:01 2012,6 errors
User.45: GND | P5V | P12V_MAIN | MB0_P12V_MAIN_R | MB0_P12V | P12V_FAN1 | P3V3_AUX | P3V3 | This gerber is just for you reference to find the differential traces in layer BOTTOM | This gerber is just for you reference to find the differential traces in layer TOP | Note:Refer to DRILL layer for ELLIPSE drill direction | 0 | 118 | 551 | 79 | FIGURE | SIZE | 16.0 | 20.0 | 29.52 | 39.0 | 40.0 | 199.0 | 223.0 | ELLIPSE | 84.0 | DRILL CHART: TOP to BOTTOM | ALL UNITS ARE IN MILS | PLATED | NON-PLATED | QTY | 448 | 18 | 48 | 4 | 1 | 3 | 2 | This gerber is just for your reference to find the SE impedance traces in layer L1. | This gerber is just for your reference to find the SE impedance traces in layer L6. | SE IMPEDANCE TABLE: L1 | SE IMPEDANCE TABLE: L6 | * - Denotes that WIDTH | is NOT used in this layer | inside board outline. | Model | SV7220G2 Mid-plane Board | PCB_NO | 13412 | VER. | 1B | Layers | DRILL | L1 | L2GND | TMASK | TPLACE | TSILK | TSMD | IMP(Ohm) | 50.0 | 60.0 | Designer | IVY LAN | WIDTH(mils) | *6.5 | *4.5 | Date | 02/05/2013 | TYPE | SE | BMASK | BPLACE | BSILK | BSMD | L3GND | L4
